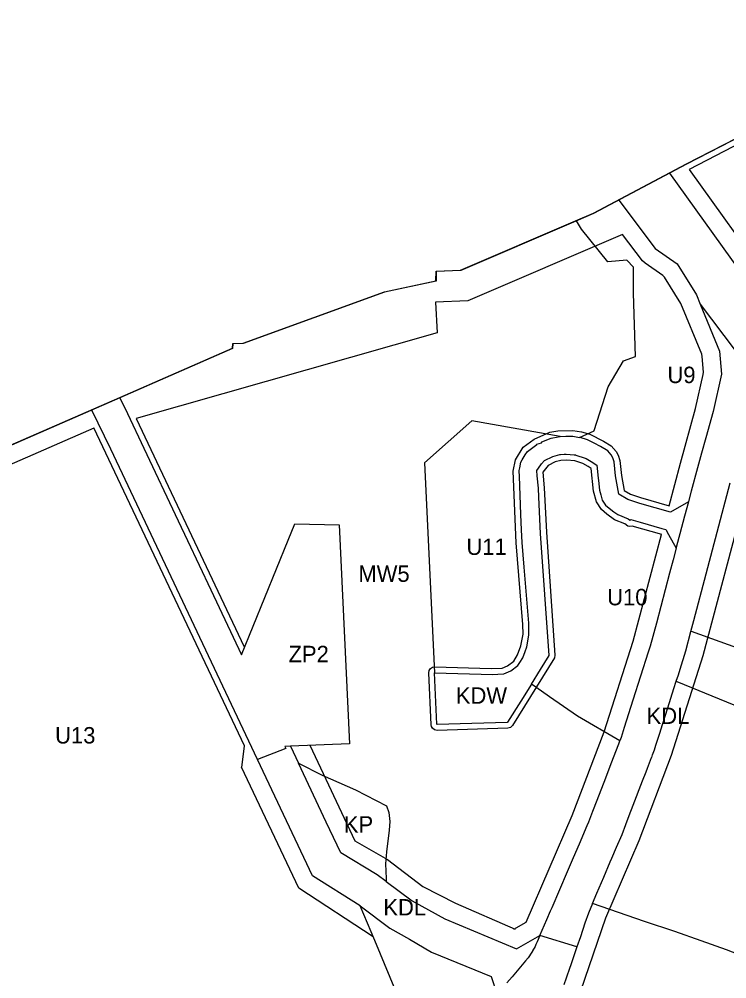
# Model space of a CAD drawing. Extents: x 7428103 to 7431580, y 5545880 to 5549002.
# Drawn here: x 7429089.8 to 7429328.8, y 5548288 to 5548612.1 of the extents above; entities that cross this region are included whole.
import ezdxf

# ---------------------------------------------------------------- set-up
doc = ezdxf.new("R2010")
doc.units = 0
for name, color, linetype in [('CZ_L_granica obszaru objętego planem', 7, 'Continuous'), ('CZ_L_linie rozgraniczające tereny o różnym przeznaczeniu oraz różnych warunkach ich zabudowy i zagospodarowania', 7, 'Continuous'), ('CZ_L_maksymalne nieprzekraczalne linie zabudowy', 7, 'Continuous'), ('CZ_L_opisy_linie rozgraniczające tereny o różnym przeznaczeniu oraz różnych warunkach ich zabudowy i zagospodarowania', 7, 'Continuous')]:
    doc.layers.add(name, color=color, linetype=linetype)

msp = doc.modelspace()

# ---------------------------------------------------------------- linework, layer by layer
at = {"layer": 'CZ_L_granica obszaru objętego planem'}
for p, q in [((7429315.24, 5548563.23), (7429352.99, 5548582.71)), ((7429283.79, 5548546.56), (7429315.24, 5548563.23)), ((7429238.94, 5548527.4), (7429277.78, 5548544)), ((7429277.78, 5548544), (7429283.79, 5548546.56)), ((7429230.59, 5548523.75), (7429230.62, 5548526.99)), ((7429230.62, 5548526.99), (7429238.94, 5548527.4)), ((7429213.23, 5548519.99), (7429230.59, 5548523.75)), ((7429165.48, 5548502.69), (7429213.23, 5548519.99)), ((7429161.84, 5548501.07), (7429162.03, 5548502.62)), ((7429162.03, 5548502.62), (7429165.48, 5548502.69)), ((7429123.84, 5548484.34), (7429161.84, 5548501.07)), ((7429079.07, 5548464.83), (7429123.84, 5548484.34))]:
    msp.add_line(p, q, dxfattribs=at)
at = {"layer": 'CZ_L_linie rozgraniczające tereny o różnym przeznaczeniu oraz różnych warunkach ich zabudowy i zagospodarowania'}
for p, q in [((7429333.08, 5548527.41), (7429309.64, 5548560.15)), ((7429292.41, 5548551.02), (7429304.68, 5548534.64)), ((7429279.75, 5548541.23), (7429278.04, 5548543.99)), ((7429288.65, 5548530.19), (7429279.75, 5548541.23)), ((7429304.68, 5548534.64), (7429312.05, 5548529.48)), ((7429295.07, 5548530.72), (7429288.65, 5548530.19)), ((7429297.31, 5548528.4), (7429295.07, 5548530.72)), ((7429297.27, 5548519.54), (7429297.31, 5548528.4)), ((7429312.05, 5548529.48), (7429318.62, 5548519)), ((7429298, 5548498.25), (7429297.27, 5548519.54)), ((7429318.62, 5548519), (7429319.88, 5548515.91)), ((7429319.88, 5548515.91), (7429326.38, 5548500.04)), ((7429319.88, 5548515.91), (7429331.62, 5548500.25)), ((7429326.38, 5548500.04), (7429327.04, 5548492.22)), ((7429288.76, 5548487.94), (7429293.9, 5548496.74)), ((7429293.9, 5548496.74), (7429298, 5548498.25)), ((7429327.04, 5548492.22), (7429324.23, 5548479.58)), ((7429284.06, 5548473.2), (7429288.76, 5548487.94)), ((7429123.88, 5548484.25), (7429126.39, 5548478.94)), ((7429120.73, 5548466.86), (7429114.39, 5548480.11)), ((7429324.23, 5548479.58), (7429321.74, 5548470.69)), ((7429126.39, 5548478.94), (7429131.92, 5548467.27)), ((7429242.67, 5548476.47), (7429226.73, 5548462.3)), ((7429272.53, 5548471.15), (7429242.67, 5548476.47)), ((7429279.05, 5548470.85), (7429284.05, 5548473.14)), ((7429284.05, 5548473.14), (7429284.06, 5548473.2)), ((7429266.26, 5548469.1), (7429266.36, 5548469.34)), ((7429266.36, 5548469.34), (7429269.48, 5548470.67)), ((7429269.48, 5548470.67), (7429271.85, 5548471.11)), ((7429271.85, 5548471.11), (7429272.53, 5548471.15)), ((7429272.53, 5548471.15), (7429274.44, 5548471.26)), ((7429274.44, 5548471.26), (7429276.78, 5548471.26)), ((7429276.78, 5548471.26), (7429279.05, 5548470.85)), ((7429279.32, 5548470.8), (7429279.05, 5548470.85)), ((7429281.81, 5548470.09), (7429279.32, 5548470.8)), ((7429284.03, 5548468.98), (7429281.81, 5548470.09)), ((7429321.74, 5548470.69), (7429320.3, 5548465.51)), ((7429170.34, 5548362.1), (7429120.73, 5548466.86)), ((7429131.92, 5548467.27), (7429143.51, 5548442.76)), ((7429260.78, 5548464.97), (7429261.47, 5548466.08)), ((7429261.47, 5548466.08), (7429263.81, 5548467.86)), ((7429263.81, 5548467.86), (7429264.62, 5548468.48)), ((7429264.62, 5548468.48), (7429264.71, 5548468.55)), ((7429264.71, 5548468.55), (7429266.26, 5548469.1)), ((7429286.2, 5548467.83), (7429284.03, 5548468.98)), ((7429288.7, 5548466.37), (7429286.2, 5548467.83)), ((7429289.73, 5548465.04), (7429288.7, 5548466.37)), ((7429259.25, 5548462.49), (7429259.76, 5548463.31)), ((7429259.76, 5548463.31), (7429260.78, 5548464.97)), ((7429266.27, 5548462), (7429267.3, 5548463.08)), ((7429267.3, 5548463.08), (7429270.1, 5548464.43)), ((7429270.1, 5548464.43), (7429272.41, 5548465.06)), ((7429272.41, 5548465.06), (7429272.61, 5548465.08)), ((7429272.61, 5548465.08), (7429273.94, 5548465.17)), ((7429273.94, 5548465.17), (7429274.59, 5548465.21)), ((7429274.59, 5548465.21), (7429277.29, 5548464.98)), ((7429277.29, 5548464.98), (7429277.7, 5548464.94)), ((7429277.7, 5548464.94), (7429277.83, 5548464.93)), ((7429277.83, 5548464.93), (7429281.02, 5548463.89)), ((7429281.02, 5548463.89), (7429281.29, 5548463.74)), ((7429281.29, 5548463.74), (7429283.07, 5548462.73)), ((7429290.35, 5548464), (7429289.73, 5548465.04)), ((7429290.8, 5548462.65), (7429290.35, 5548464)), ((7429320.3, 5548465.51), (7429318.94, 5548460.65)), ((7429226.73, 5548462.3), (7429230.14, 5548391.41)), ((7429258.71, 5548459.44), (7429258.75, 5548459.65)), ((7429258.75, 5548459.65), (7429258.91, 5548460.56)), ((7429258.91, 5548460.56), (7429259.25, 5548462.49)), ((7429264.61, 5548459.71), (7429265.18, 5548460.49)), ((7429264.83, 5548457.88), (7429264.61, 5548459.71)), ((7429265.18, 5548460.49), (7429266.27, 5548462)), ((7429283.07, 5548462.73), (7429284.92, 5548461.52)), ((7429284.92, 5548461.52), (7429285.37, 5548457.16)), ((7429291.29, 5548457.88), (7429290.8, 5548462.65)), ((7429318.94, 5548460.65), (7429316.82, 5548452.76)), ((7429258.78, 5548457.8), (7429258.71, 5548459.44)), ((7429259.26, 5548444.81), (7429258.78, 5548457.8)), ((7429265.19, 5548453.7), (7429264.83, 5548457.88)), ((7429285.37, 5548457.16), (7429285.46, 5548456.29)), ((7429292.32, 5548451.68), (7429291.29, 5548457.88)), ((7429265.33, 5548450.72), (7429265.19, 5548453.7)), ((7429285.46, 5548456.29), (7429285.79, 5548453.09)), ((7429285.79, 5548453.09), (7429286.27, 5548451.45)), ((7429325.56, 5548438.86), (7429329.96, 5548455.51)), ((7429265.91, 5548438.4), (7429265.33, 5548450.72)), ((7429286.27, 5548451.45), (7429286.78, 5548449.71)), ((7429295.41, 5548449.95), (7429292.32, 5548451.68)), ((7429299.47, 5548448.55), (7429295.41, 5548449.95)), ((7429316.82, 5548452.76), (7429315.88, 5548449.21)), ((7429286.78, 5548449.71), (7429287.89, 5548447.96)), ((7429287.89, 5548447.96), (7429289.61, 5548446.5)), ((7429309.8, 5548445.6), (7429299.47, 5548448.55)), ((7429315.85, 5548449.08), (7429309.8, 5548445.6)), ((7429315.85, 5548449.08), (7429314.57, 5548444.24)), ((7429315.88, 5548449.21), (7429315.85, 5548449.08)), ((7429259.49, 5548439.66), (7429259.26, 5548444.81)), ((7429289.61, 5548446.5), (7429290.65, 5548445.75)), ((7429290.65, 5548445.75), (7429291.04, 5548445.47)), ((7429291.04, 5548445.47), (7429291.99, 5548444.79)), ((7429291.99, 5548444.79), (7429295.5, 5548443.33)), ((7429314.57, 5548444.24), (7429313, 5548438.29)), ((7429143.51, 5548442.76), (7429146.68, 5548436.06)), ((7429180.67, 5548436.17), (7429182.91, 5548441.72)), ((7429182.91, 5548441.72), (7429197.91, 5548441.33)), ((7429197.91, 5548441.33), (7429201.43, 5548367.39)), ((7429295.5, 5548443.33), (7429295.92, 5548443)), ((7429295.92, 5548443), (7429296.19, 5548442.79)), ((7429296.19, 5548442.79), (7429296.32, 5548443.04)), ((7429296.32, 5548443.04), (7429296.36, 5548443.12)), ((7429296.36, 5548443.12), (7429299.6, 5548442.24)), ((7429299.6, 5548442.24), (7429306.91, 5548440.13)), ((7429306.91, 5548440.13), (7429308.25, 5548439.74)), ((7429259.69, 5548435.44), (7429259.49, 5548439.66)), ((7429268.79, 5548397.21), (7429265.91, 5548438.4)), ((7429308.25, 5548439.74), (7429309.18, 5548438.09)), ((7429309.18, 5548438.09), (7429311.73, 5548433.51)), ((7429313, 5548438.29), (7429311.89, 5548434.1)), ((7429322.42, 5548426.98), (7429325.56, 5548438.86)), ((7429146.68, 5548436.06), (7429154.57, 5548419.39)), ((7429164.96, 5548397.41), (7429180.67, 5548436.17)), ((7429260.39, 5548427.04), (7429259.69, 5548435.44)), ((7429311.89, 5548434.1), (7429311.73, 5548433.51)), ((7429311.73, 5548433.51), (7429310.69, 5548429.58)), ((7429310.69, 5548429.58), (7429309.5, 5548425.07)), ((7429261.96, 5548408.13), (7429260.39, 5548427.04)), ((7429309.5, 5548425.07), (7429305.04, 5548408.18)), ((7429317.69, 5548409.08), (7429321.84, 5548424.8)), ((7429321.84, 5548424.8), (7429322.42, 5548426.98)), ((7429154.57, 5548419.39), (7429164.96, 5548397.41)), ((7429262.01, 5548404.13), (7429261.96, 5548408.13)), ((7429305.04, 5548408.18), (7429302.91, 5548400.33)), ((7429316.7, 5548405.36), (7429317.69, 5548409.08)), ((7429314.98, 5548398.84), (7429316.7, 5548405.36)), ((7429316.88, 5548405.29), (7429316.7, 5548405.36)), ((7429373.74, 5548384.85), (7429316.88, 5548405.29)), ((7429261.26, 5548400.2), (7429262.01, 5548404.13)), ((7429259.94, 5548396.41), (7429260.69, 5548398.57)), ((7429260.69, 5548398.57), (7429261.26, 5548400.2)), ((7429302.29, 5548398.4), (7429297.12, 5548382.09)), ((7429302.91, 5548400.33), (7429302.29, 5548398.4)), ((7429313.05, 5548392.63), (7429314.98, 5548398.84)), ((7429258.29, 5548393.89), (7429258.95, 5548394.9)), ((7429258.95, 5548394.9), (7429259.94, 5548396.41)), ((7429265.89, 5548392.55), (7429268.79, 5548397.21)), ((7429253.56, 5548391.02), (7429255.9, 5548392.06)), ((7429255.9, 5548392.06), (7429258.29, 5548393.89)), ((7429262.81, 5548387.59), (7429265.89, 5548392.55)), ((7429312.46, 5548390.75), (7429313.05, 5548392.63)), ((7429230.14, 5548391.37), (7429230.14, 5548391.41)), ((7429230.14, 5548391.41), (7429249.81, 5548390.78)), ((7429230.94, 5548374.03), (7429230.14, 5548391.37)), ((7429249.81, 5548390.78), (7429251.51, 5548390.89)), ((7429251.51, 5548390.89), (7429253.56, 5548391.02)), ((7429310.98, 5548386.09), (7429311.75, 5548388.53)), ((7429311.75, 5548388.53), (7429312.46, 5548390.75)), ((7429262.81, 5548387.59), (7429259.24, 5548381.85)), ((7429263.23, 5548387.29), (7429262.81, 5548387.59)), ((7429266.19, 5548385.23), (7429263.23, 5548387.29)), ((7429268.98, 5548383.3), (7429266.19, 5548385.23)), ((7429308.92, 5548379.6), (7429310.98, 5548386.09)), ((7429259.24, 5548381.85), (7429254.8, 5548374.71)), ((7429278.43, 5548376.72), (7429268.98, 5548383.3)), ((7429297.12, 5548382.09), (7429294.21, 5548372.93)), ((7429307.11, 5548373.88), (7429308.92, 5548379.6)), ((7429292.73, 5548368.45), (7429278.43, 5548376.72)), ((7429230.95, 5548373.94), (7429230.94, 5548374.03)), ((7429242.74, 5548374.29), (7429230.95, 5548373.94)), ((7429254.76, 5548374.65), (7429242.74, 5548374.29)), ((7429254.8, 5548374.71), (7429254.76, 5548374.65)), ((7429294.21, 5548372.93), (7429293.12, 5548369.48)), ((7429306.16, 5548371), (7429307.11, 5548373.88)), ((7429293.12, 5548369.48), (7429292.73, 5548368.45)), ((7429304.91, 5548366.96), (7429306.18, 5548370.99)), ((7429306.18, 5548370.99), (7429306.16, 5548371)), ((7429179.88, 5548365.87), (7429170.34, 5548362.1)), ((7429181.52, 5548366.62), (7429179.56, 5548366.55)), ((7429179.56, 5548366.55), (7429179.88, 5548365.87)), ((7429201.43, 5548367.39), (7429181.52, 5548366.62)), ((7429181.52, 5548366.62), (7429184.19, 5548360.91)), ((7429289.8, 5548360.81), (7429292.34, 5548367.43)), ((7429292.34, 5548367.43), (7429292.7, 5548368.39)), ((7429292.7, 5548368.39), (7429292.73, 5548368.45)), ((7429304.39, 5548365.34), (7429304.91, 5548366.96)), ((7429302.02, 5548359.16), (7429303.43, 5548362.83)), ((7429303.43, 5548362.83), (7429303.45, 5548362.83)), ((7429303.45, 5548362.83), (7429303.74, 5548363.7)), ((7429303.74, 5548363.7), (7429304.39, 5548365.34)), ((7429188.95, 5548322.79), (7429170.34, 5548362.1)), ((7429193.53, 5548340.93), (7429184.19, 5548360.91)), ((7429184.19, 5548360.91), (7429192.19, 5548356.8)), ((7429287.95, 5548355.97), (7429289.8, 5548360.81)), ((7429301.55, 5548357.93), (7429302.02, 5548359.16)), ((7429192.19, 5548356.8), (7429203.4, 5548351.91)), ((7429285.04, 5548348.39), (7429287.95, 5548355.97)), ((7429300.37, 5548354.85), (7429301.55, 5548357.93)), ((7429297.23, 5548346.65), (7429300.37, 5548354.85)), ((7429203.4, 5548351.91), (7429213.93, 5548346.41)), ((7429213.93, 5548346.41), (7429214.66, 5548344.23)), ((7429283.58, 5548344.7), (7429285.04, 5548348.39)), ((7429295.9, 5548343.19), (7429297.23, 5548346.65)), ((7429214.66, 5548344.23), (7429215.06, 5548341.16)), ((7429282.22, 5548341.02), (7429283.58, 5548344.7)), ((7429294.72, 5548340.11), (7429295.9, 5548343.19)), ((7429198.42, 5548330.59), (7429193.53, 5548340.93)), ((7429215.06, 5548341.16), (7429214.74, 5548338.24)), ((7429279.04, 5548333.63), (7429281.7, 5548339.8)), ((7429281.7, 5548339.8), (7429282.22, 5548341.02)), ((7429293.46, 5548336.83), (7429294.72, 5548340.11)), ((7429214.74, 5548338.24), (7429213.93, 5548330.96)), ((7429291.61, 5548332.49), (7429293.46, 5548336.83)), ((7429277.03, 5548328.97), (7429279.04, 5548333.63)), ((7429210.7, 5548323.15), (7429198.42, 5548330.59)), ((7429213.93, 5548330.96), (7429213.6, 5548326.9)), ((7429290.04, 5548328.84), (7429291.61, 5548332.49)), ((7429213.6, 5548326.9), (7429213.83, 5548321.88)), ((7429275, 5548324.26), (7429277.03, 5548328.97)), ((7429287.24, 5548322.33), (7429289.48, 5548327.53)), ((7429289.48, 5548327.53), (7429290.04, 5548328.84)), ((7429269.79, 5548312.14), (7429275, 5548324.26)), ((7429205.02, 5548312.72), (7429188.95, 5548322.79)), ((7429213.78, 5548320.89), (7429210.7, 5548323.15)), ((7429213.83, 5548321.88), (7429213.78, 5548320.89)), ((7429213.78, 5548320.89), (7429222.6, 5548314.4)), ((7429284.94, 5548316.99), (7429287.24, 5548322.33)), ((7429283.45, 5548313.44), (7429284.94, 5548316.99)), ((7429222.6, 5548314.4), (7429233.58, 5548308.32)), ((7429209.95, 5548300.95), (7429205.02, 5548312.72)), ((7429205.02, 5548312.72), (7429215.04, 5548305.17)), ((7429268.01, 5548308.02), (7429269.28, 5548310.97)), ((7429269.28, 5548310.97), (7429269.79, 5548312.14)), ((7429283.45, 5548313.44), (7429282.1, 5548310.25)), ((7429300.98, 5548307.36), (7429283.45, 5548313.44)), ((7429233.58, 5548308.32), (7429257.79, 5548298.16)), ((7429265.71, 5548302.68), (7429268.01, 5548308.02)), ((7429282.1, 5548310.25), (7429280.92, 5548306.79)), ((7429311.27, 5548303.99), (7429300.98, 5548307.36)), ((7429215.04, 5548305.17), (7429221.69, 5548301.41)), ((7429280.92, 5548306.79), (7429279.36, 5548302.24)), ((7429219.15, 5548278.95), (7429209.95, 5548300.95)), ((7429221.69, 5548301.41), (7429229.11, 5548297.07)), ((7429257.79, 5548298.16), (7429265.71, 5548302.68)), ((7429265.71, 5548302.68), (7429264.81, 5548300.58)), ((7429278.18, 5548298.81), (7429265.71, 5548302.68)), ((7429279.36, 5548302.24), (7429278.18, 5548298.81)), ((7429320.2, 5548300.85), (7429311.27, 5548303.99)), ((7429328.77, 5548297.85), (7429320.2, 5548300.85)), ((7429264.06, 5548299), (7429263.18, 5548297.45)), ((7429264.38, 5548299.67), (7429264.06, 5548299)), ((7429264.81, 5548300.58), (7429264.38, 5548299.67)), ((7429278.18, 5548298.81), (7429276.01, 5548292.48)), ((7429339.94, 5548293.49), (7429328.77, 5548297.85)), ((7429229.11, 5548297.07), (7429249.29, 5548288.8)), ((7429261.79, 5548295.18), (7429260.87, 5548294.09)), ((7429262.93, 5548297), (7429261.79, 5548295.18)), ((7429263.16, 5548297.42), (7429262.93, 5548297)), ((7429263.18, 5548297.45), (7429263.16, 5548297.42)), ((7429260.87, 5548294.09), (7429256.3, 5548288.71)), ((7429275.8, 5548291.87), (7429274.55, 5548288.21)), ((7429276.01, 5548292.48), (7429275.8, 5548291.87)), ((7429249.29, 5548288.8), (7429249.28, 5548288.79)), ((7429249.28, 5548288.79), (7429251.17, 5548282.96)), ((7429256.3, 5548288.71), (7429254.54, 5548286.65)), ((7429274.55, 5548288.21), (7429273.79, 5548285.99))]:
    msp.add_line(p, q, dxfattribs=at)
for points in [[(7429353, 5548582.61), (7429315.25, 5548563.12), (7429315.25, 5548563.12), (7429283.8, 5548546.45), (7429277.79, 5548543.89), (7429238.95, 5548527.29), (7429230.63, 5548526.88), (7429230.61, 5548523.64), (7429213.25, 5548519.88), (7429165.49, 5548502.58), (7429162.04, 5548502.51), (7429161.85, 5548500.96), (7429123.85, 5548484.23), (7429079.08, 5548464.72)], [(7429311.75, 5548388.53), (7429311.92, 5548388.46), (7429364.74, 5548366.81), (7429364.8, 5548366.69)]]:
    msp.add_lwpolyline(points, dxfattribs=at)
at = {"layer": 'CZ_L_maksymalne nieprzekraczalne linie zabudowy'}
for points in [[(7429343.23, 5548523.88), (7429413.91, 5548612.11), (7429316.15, 5548561.37), (7429343.22, 5548523.54)], [(7429306.91, 5548438.05), (7429296.92, 5548440.9), (7429296.13, 5548440.79), (7429295.38, 5548440.96), (7429294.35, 5548441.64), (7429290.95, 5548443.08), (7429288.35, 5548444.94), (7429286.53, 5548446.5), (7429284.86, 5548449.13), (7429283.82, 5548452.75), (7429283.02, 5548460.37), (7429282.04, 5548461.01), (7429280.24, 5548462.04), (7429277.5, 5548462.94), (7429274.67, 5548463.2), (7429272.82, 5548463.09), (7429270.9, 5548462.58), (7429268.47, 5548461.41), (7429266.69, 5548459.14), (7429267.19, 5548453.8), (7429267.89, 5548438.9), (7429270.79, 5548397.35), (7429270.62, 5548396.4), (7429256.45, 5548373.59), (7429255.72, 5548372.89), (7429254.84, 5548372.65), (7429231.01, 5548371.94), (7429230.13, 5548372.12), (7429229.41, 5548372.66), (7429229.08, 5548373.22), (7429228.95, 5548373.83), (7429228.14, 5548391.33), (7429228.26, 5548392.11), (7429228.76, 5548392.86), (7429229.42, 5548393.28), (7429230.18, 5548393.41), (7429249.21, 5548392.8), (7429252.96, 5548392.98), (7429254.79, 5548393.76), (7429256.87, 5548395.37), (7429258.18, 5548397.45), (7429259.24, 5548400.5), (7429260, 5548404.42), (7429259.97, 5548407.75), (7429257.69, 5548435.32), (7429256.71, 5548459.49), (7429257.42, 5548463.3), (7429260.1, 5548467.54), (7429263.76, 5548470.31), (7429269.11, 5548472.63), (7429271.72, 5548473.11), (7429276.84, 5548473.26), (7429279.75, 5548472.75), (7429282.51, 5548471.97), (7429287.14, 5548469.59), (7429289.77, 5548468.05), (7429291.44, 5548466.08), (7429292.17, 5548464.84), (7429292.74, 5548463.11), (7429293.29, 5548458.01), (7429294.18, 5548452.93), (7429296.29, 5548451.76), (7429299.72, 5548450.58), (7429309.31, 5548447.82), (7429313.14, 5548462.2), (7429318.29, 5548480.63), (7429320.87, 5548492.11), (7429320.96, 5548492.89), (7429320.51, 5548498.22), (7429320.34, 5548498.95), (7429313.31, 5548516.13), (7429307.79, 5548524.99), (7429307.22, 5548525.54), (7429301.22, 5548529.74), (7429300.34, 5548530.5), (7429293.63, 5548539.35), (7429241.34, 5548517), (7429230.45, 5548516.5), (7429231.04, 5548506.18), (7429129.39, 5548477.29), (7429165.81, 5548400.16)], [(7429115.1, 5548473.99), (7429037.11, 5548440.01), (7429015.52, 5548430.78), (7429049.45, 5548356.05), (7429058.81, 5548336.55), (7429096.56, 5548250.96), (7429126.15, 5548245.63), (7429130.98, 5548244.54)], [(7429164.99, 5548359.38), (7429165.92, 5548366.77), (7429115.06, 5548474.08)], [(7429341.66, 5548475.02), (7429335.21, 5548451.88), (7429320.74, 5548397.16), (7429310.09, 5548363.49), (7429299.06, 5548334.66), (7429287.9, 5548308.54), (7429279.42, 5548283.92), (7429270.71, 5548265.21)], [(7429256.94, 5548304.79), (7429261.11, 5548307.17), (7429276.65, 5548343.25), (7429287.45, 5548371.46), (7429297.15, 5548402.02), (7429306.74, 5548438.09)], [(7429188.05, 5548366.97), (7429203.23, 5548334.65), (7429214.2, 5548328.32), (7429226.21, 5548319.22), (7429237.2, 5548313.54), (7429257.31, 5548304.81)], [(7429209.43, 5548302.18), (7429184.26, 5548318.69), (7429164.92, 5548359.54)]]:
    msp.add_lwpolyline(points, dxfattribs=at)

# ---------------------------------------------------------------- texts
at = {"layer": 'CZ_L_opisy_linie rozgraniczające tereny o różnym przeznaczeniu oraz różnych warunkach ich zabudowy i zagospodarowania'}
for s, p in [('U9', (7429308.78, 5548489.22)), ('U11', (7429240.89, 5548431.19)), ('MW5', (7429204.4, 5548422.1)), ('U10', (7429288.42, 5548414.18)), ('ZP2', (7429180.81, 5548394.95)), ('KDW', (7429237.31, 5548380.94)), ('KDL', (7429301.74, 5548374.11)), ('U13', (7429101.96, 5548367.51)), ('KP', (7429199.49, 5548337.41)), ('KDL', (7429212.83, 5548309.43))]:
    msp.add_text(s, height=5.549, dxfattribs=at).set_placement(p)

doc.saveas('drawing.dxf')
